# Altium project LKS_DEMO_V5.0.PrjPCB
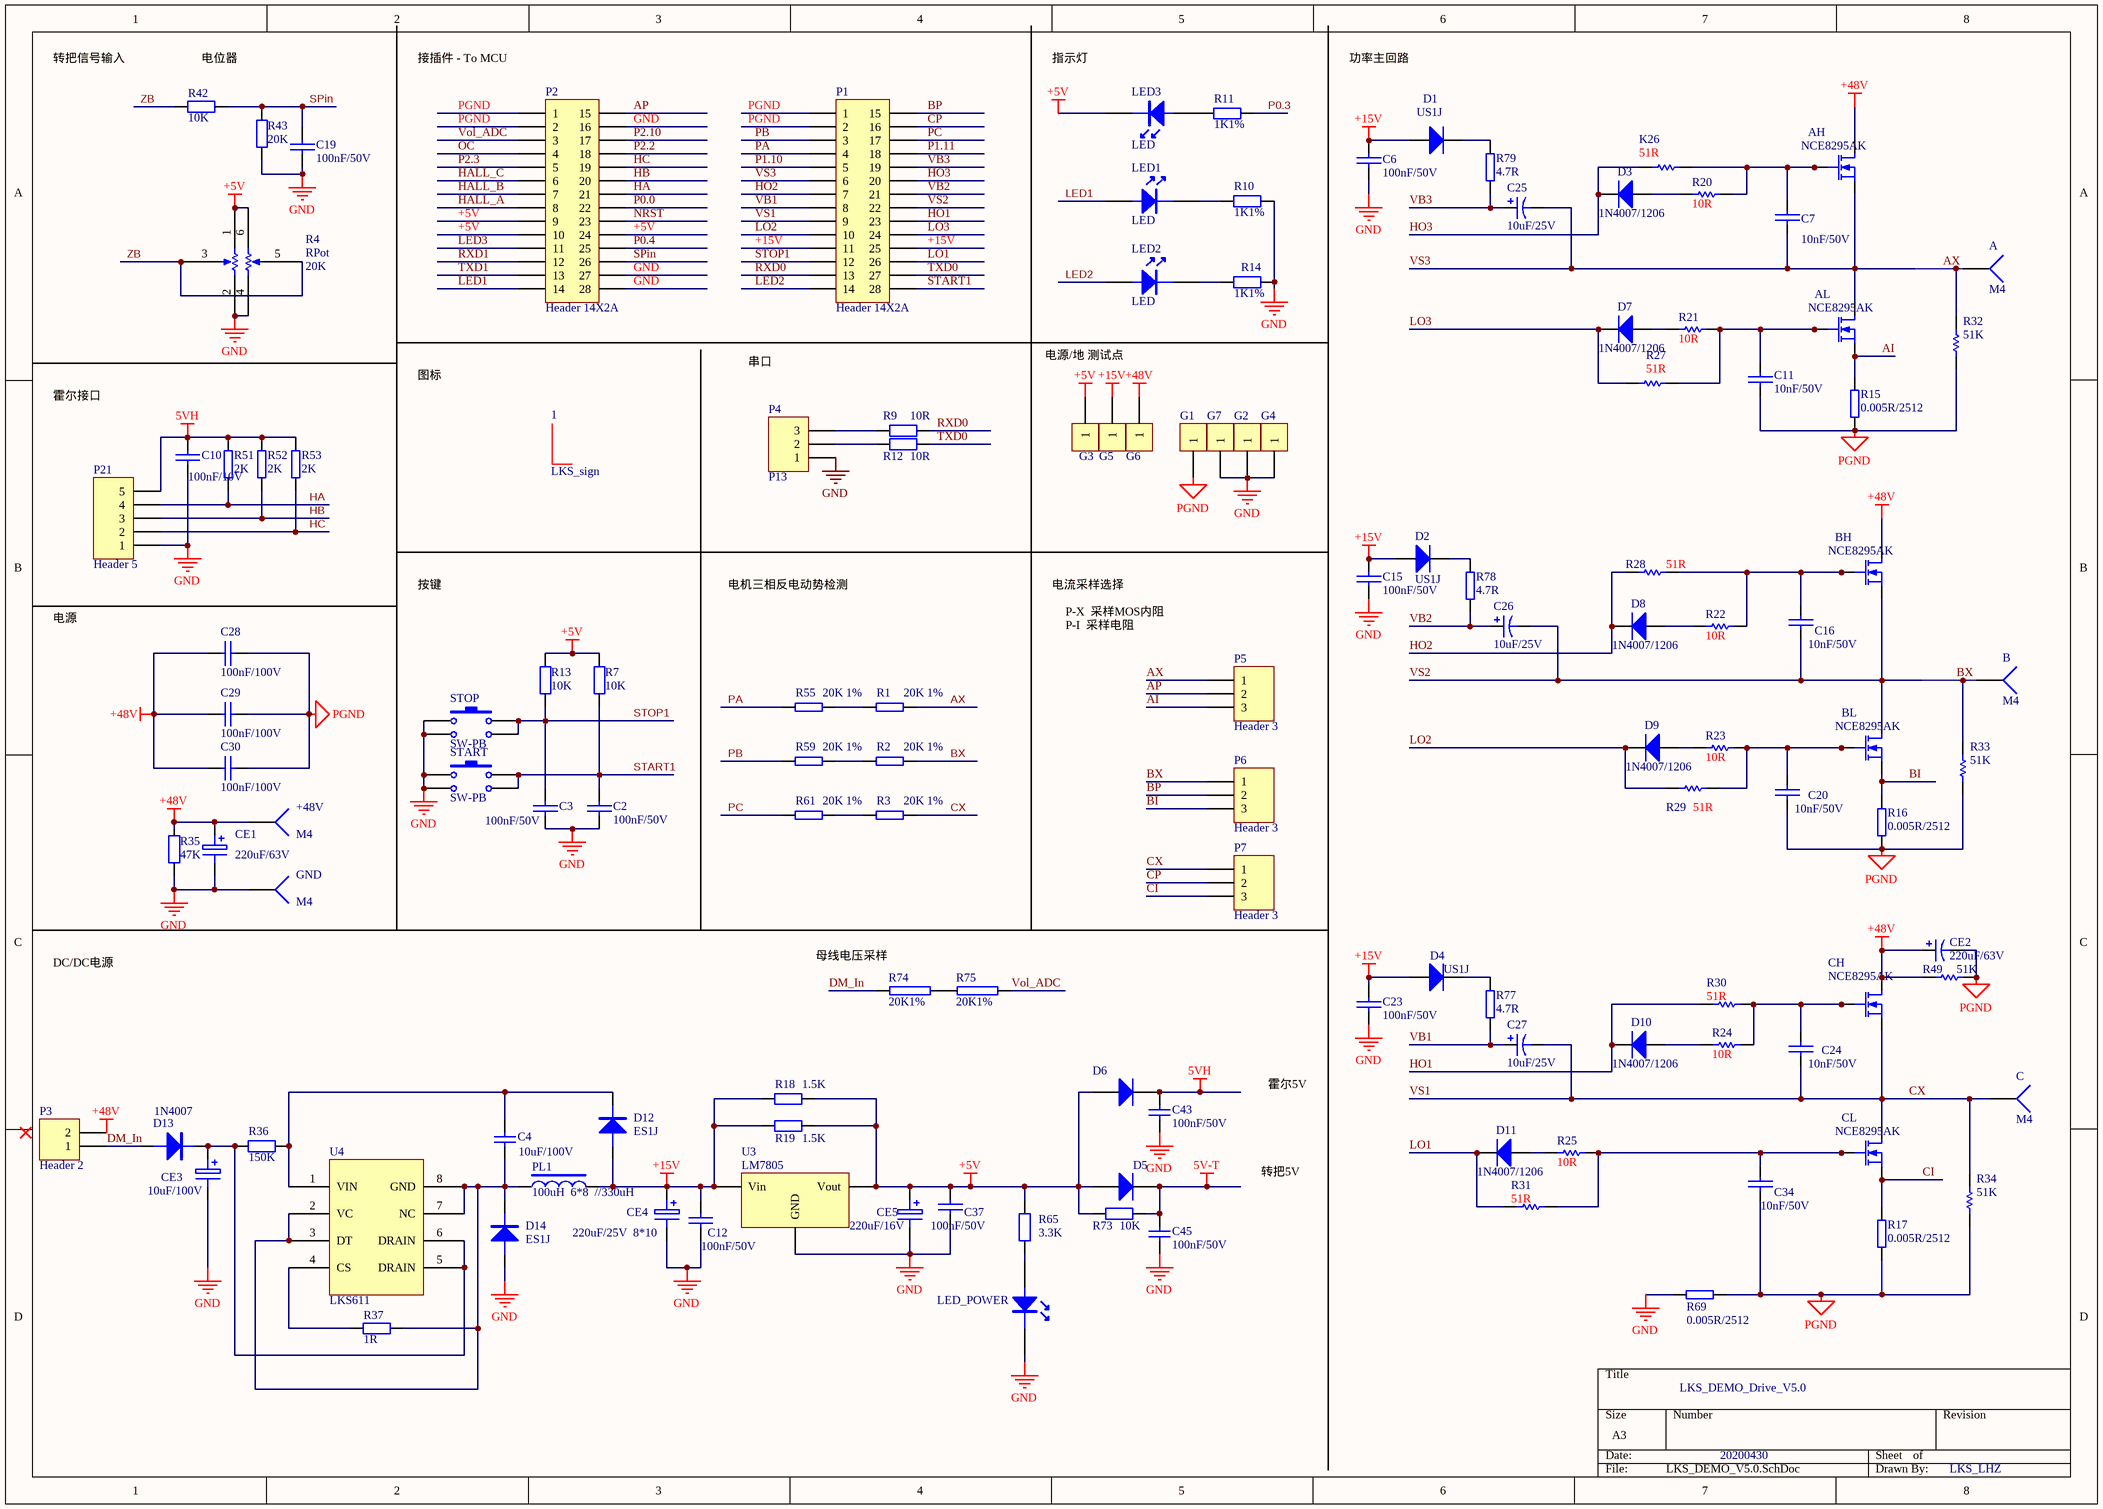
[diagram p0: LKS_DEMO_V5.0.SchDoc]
1 sheet, 130 parts. Net scope: global (net labels, ports and power ports of the same name join across sheets).
Board file: LKS_DEMO_V5.0.PcbDoc

## Sheet LKS_DEMO_V5.0.SchDoc
size A3

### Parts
1  LKS_sign  [LKS_LOGO2]
+48V  M4  [M4_Conector]
A  M4  [M4_Conector]
AH  NCE8295AK  [TO-252]
AL  NCE8295AK  [TO-252]
B  M4  [M4_Conector]
BH  NCE8295AK  [TO-252]
BL  NCE8295AK  [TO-252]
C  M4  [M4_Conector]
C2  100nF/50V  [0603C]
C3  100nF/50V  [0603C]
C4  10uF/100V  [1206]
C6  100nF/50V  [0603C]
C7  10nF/50V  [0603C]
C10  100nF/10V  [0603C]
C11  10nF/50V  [0603C]
C12  100nF/50V  [0603C]
C15  100nF/50V  [0603C]
C16  10nF/50V  [0603C]
C19  100nF/50V  [0603C]
C20  10nF/50V  [0603C]
C23  100nF/50V  [0603C]
C24  10nF/50V  [0603C]
C25  10uF/25V  [1206]
C26  10uF/25V  [1206]
C27  10uF/25V  [1206]
C28  100nF/100V  [0805C]
C29  100nF/100V  [0805C]
C30  100nF/100V  [0805C]
C34  10nF/50V  [0603C]
C37  100nF/50V  [0603C]
C43  100nF/50V  [0603C]
C45  100nF/50V  [0603C]
CE1  220uF/63V  [220uF/25V 12.5*12.5]
CE2  220uF/63V  [220uF/25V 12.5*12.5]
CE3  10uF/100V  [220UF/25V paster8*10]
CE4  220uF/25V  8*10  [220UF/25V paster8*10]
CE5  220uF/16V  [220UF/16V paster6.3*7.7 - duplicate]
CH  NCE8295AK  [TO-252]
CL  NCE8295AK  [TO-252]
D1  US1J  [SMA金丰]
D2  US1J  [SMA金丰]
D3  1N4007/1206  [D1206]
D4  US1J  [SMA金丰]
D5  1N4007  [D1206]  (value not drawn)
D6  1N4007  [D1206]  (value not drawn)
D7  1N4007/1206  [D1206]
D8  1N4007/1206  [D1206]
D9  1N4007/1206  [D1206]
D10  1N4007/1206  [D1206]
D11  1N4007/1206  [D1206]
D12  ES1J  [DO-214AC]
D13  1N4007  [DO-214AC]
D14  ES1J  [DO-214AC]
G1  PAD1.2  [PAD1.2]  (value not drawn)
G2  PAD1.2  [PAD1.2]  (value not drawn)
G3  PAD1.2  [PAD1.2]  (value not drawn)
G4  PAD1.2  [PAD1.2]  (value not drawn)
G5  PAD1.2  [PAD1.2]  (value not drawn)
G6  PAD1.2  [PAD1.2]  (value not drawn)
G7  PAD1.2  [PAD1.2]  (value not drawn)
GND  M4  [M4_Conector]
K26  51R  [0805R]
LED1  LED  [SOD323]
LED2  LED  [SOD323]
LED3  LED  [SOD323]
LED_POWER  LED_R  [SOD323]  (value not drawn)
P1  Header 14X2A  [HDR2X14_CEN]
P2  Header 14X2A  [HDR2X14_CEN]
P3  Header 2  [HDR1X2]
P4  P13  [2.54-XH-3A-180]
P5  Header 3  [HDR1X3]
P6  Header 3  [HDR1X3]
P7  Header 3  [HDR1X3]
P21  Header 5  [2.54-XH-5A-180]
PL1  100uH  6*8  //330uH  [L_DIP_6*8MM]
R1  20K 1%  [0805R]
R2  20K 1%  [0805R]
R3  20K 1%  [0805R]
R4  RPot  value 20K  [RK097-W]
R7  10K  [0603R]
R9  10R  [0603R]
R10  1K1%  [0603R]
R11  1K1%  [0603R]
R12  10R  [0603R]
R13  10K  [0603R]
R14  1K1%  [0603R]
R15  0.005R/2512  [2512]
R16  0.005R/2512  [2512]
R17  0.005R/2512  [2512]
R18  1.5K  [0805R]
R19  1.5K  [0805R]
R20  10R  [0805R]
R21  10R  [0805R]
R22  10R  [0805R]
R23  10R  [0805R]
R24  10R  [0805R]
R25  10R  [0805R]
R27  51R  [0805R]
R28  51R  [0805R]
R29  51R  [0805R]
R30  51R  [0805R]
R31  51R  [0805R]
R32  51K  [0805R]
R33  51K  [0805R]
R34  51K  [0805R]
R35  47K  [1206R]
R36  150K  [0805R]
R37  1R  [1206]
R42  10K  [0603R]
R43  20K  [0603R]
R49  51K  [0805R]
R51  2K  [0603R]
R52  2K  [0603R]
R53  2K  [0603R]
R55  20K 1%  [0805R]
R59  20K 1%  [0805R]
R61  20K 1%  [0805R]
R65  3.3K  [0603R]
R69  0.005R/2512  [2512]
R73  10K  [0603R]
R74  20K1%  [0603R]
R75  20K1%  [0603R]
R77  4.7R  [0805r]
R78  4.7R  [0805r]
R79  4.7R  [0805r]
START  SW-PB  [SW-PB  12*12]
STOP  SW-PB  [SW-PB  12*12]
U3  LM7805  [SOT-89]
U4  LKS611

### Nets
5V-T: C45.2 D5.2(K) R73.2
5VH: C10.1 C43.2 D6.2(K) P21.5 R51.2 R52.2 R53.2
+5V: C37.2 CE5.1 D5.1(A) D6.1(A) G3.1 LED3.2(K) P2.9 P2.10 P2.24 R4.1(TOP) R4.6(TOP) R7.1 R13.2 R18.2 R19.2 R65.1 R73.1 U3.1(Vout)
+15V: C6.2 C12.1 C15.2 C23.2 CE4.1 D1.1(A) D2.1(A) D4.1(A) D12.1 G5.1 P1.11 P1.25 PL1.1 R18.1 R19.1 U3.3(Vin)
+48V: +48V.1 AH.2(D) BH.2(D) C28.2 C29.2 C30.2 CE1.1 CE2.1 CH.2(D) G6.1 P3.2 R35.1 R49.1
GND: C2.1 C3.2 C6.1 C10.2 C12.2 C15.1 C19.1 C23.1 C37.1 C43.1 C45.1 CE1.2 CE3.2 CE4.2 CE5.2 D14.1 G2.1 G4.1 G7.1 GND.1 LED_POWER.2(K) P2.16 P2.27 P2.28 P4.1 P21.1 R4.2(TAP) R4.4(BOT) R10.2 R14.2 R35.2 R43.1 R69.2 START.1 START.3 STOP.1 STOP.3 U3.2(GND)
PGND: C11.2 C20.2 C28.1 C29.1 C30.1 C34.2 CE2.2 G1.1 P1.1 P1.2 P2.1 P2.2 R15.2 R16.1 R17.2 R32.1 R33.1 R34.1 R49.2 R69.1
AI: AL.3(S) P5.3 R15.1
AP: P2.15 P5.2
AX: A.1 AH.3(S) AL.2(D) C7.2 C25.2 P1.6 P5.1 R1.2 R32.2  [also labelled VS3]
BI: BL.3(S) P6.3 R16.2
BP: P1.15 P6.2
BX: B.1 BH.3(S) BL.2(D) C16.2 C26.2 P1.22 P6.1 R2.2 R33.2  [also labelled VS2]
CI: CL.3(S) P7.3 R17.1
CP: P1.16 P7.2
CX: C.1 C24.2 C27.2 CH.3(S) CL.2(D) P1.9 P7.1 R3.2 R34.2  [also labelled VS1]
DM_In: D13.1 P3.1 R74.1
HA: P2.21 P21.4 R51.1
HALL_A: P2.8
HALL_B: P2.7
HALL_C: P2.6
HB: P2.20 P21.3 R52.1
HC: P2.19 P21.2 R53.1
HO1: D10.2(K) P1.23 R30.1
HO2: D8.2(K) P1.7 R28.1
HO3: D3.2(K) K26.1 P1.20
LED1: LED1.1(A) P2.14
LED2: LED2.1(A) P1.14
LED3: P2.11
LO1: D11.2(K) P1.26 R31.1
LO2: D9.2(K) P1.10 R29.1
LO3: D7.2(K) P1.24 R27.1
NRST: P2.23
OC: P2.4
P0.0: P2.22
P0.3: R11.2
P0.4: P2.25
P1.10: P1.5
P1.11: P1.18
P2.2: P2.18
P2.3: P2.5
P2.10: P2.17
PA: P1.4 R55.1
PB: P1.3 R59.1
PC: P1.17 R61.1
RXD0: P1.13 R9.1
RXD1: P2.12
SPin: C19.2 P2.26 R42.2 R43.2
START1: C2.2 P1.28 R7.2 START.2 START.4
STOP1: C3.1 P1.12 R13.1 STOP.2 STOP.4
TXD0: P1.27 R12.2
TXD1: P2.13
VB1: C27.1 P1.8 R77.1
VB2: C26.1 P1.21 R78.1
VB3: C25.1 P1.19 R79.1
Vol_ADC: P2.3 R75.2
ZB: R4.3(BOT) R4.5(TAP) R42.1
NetAH_1: AH.1(G) C7.1 K26.2 R20.1
NetAL_1: AL.1(G) C11.1 R21.1 R27.2
NetBH_1: BH.1(G) C16.1 R22.1 R28.2
NetBL_1: BL.1(G) C20.1 R23.1 R29.2
NetC4_1: C4.1 D12.2 R36.1 U4.1(VIN)
NetC4_2: C4.2 D14.2 PL1.2 R37.2 U4.2(VC) U4.3(DT) U4.7(NC) U4.8(GND)
NetC24_1: C24.1 CH.1(G) R24.1 R30.2
NetC34_1: C34.1 CL.1(G) R25.1 R31.2
NetCE3_1: CE3.1 D13.2 R36.2 U4.5(DRAIN) U4.6(DRAIN)
NetD1_2: D1.2(K) R79.2
NetD2_2: D2.2(K) R78.2
NetD3_1: D3.1(A) R20.2
NetD4_2: D4.2(K) R77.2
NetD7_1: D7.1(A) R21.2
NetD8_1: D8.1(A) R22.2
NetD9_1: D9.1(A) R23.2
NetD10_1: D10.1(A) R24.2
NetD11_1: D11.1(A) R25.2
NetLED1_2: LED1.2(K) R10.1
NetLED2_2: LED2.2(K) R14.1
NetLED3_1: LED3.1(A) R11.1
NetLED_POWER_1: LED_POWER.1(A) R65.2
NetP4_2: P4.2 R12.1
NetP4_3: P4.3 R9.2
NetR1_1: R1.1 R55.2
NetR2_1: R2.1 R59.2
NetR3_1: R3.1 R61.2
NetR37_1: R37.1 U4.4(CS)
NetR74_2: R74.2 R75.1

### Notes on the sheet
- 转把信号输入
- (near R42) 电位器
- 接插件 - To MCU
- 指示灯
- 功率主回路
- 图标
- 串口
- 电源/地 测试点
- 霍尔接口
- 按键
- 电机三相反电动势检测
- 电流采样选择
- 电源
- P-X  采样MOS内阻
- P-I  采样电阻
- DC/DC电源
- (near R74) 母线电压采样
- LKS_DEMO_Drive_V5.0
- 20200430
- LKS_LHZ
- Labels drawn without touching a wire or pin: 转把5V, 霍尔5V

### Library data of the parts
+48V A B C GND = Socket
AH AL BH BL CH CL = MOS
C2 C3 C7 C10-C12 C16 C20 C24 C28-C30 C34 = CAP: Capacitor
C4 = Cap: Capacitor
C6 C15 C19 C23 C37 = C: Capacitor
C25-C27 = Cap Pol1: Polarized Capacitor (Radial); Value: 47uF/50V
C43 C45 = Cap: Capacitor; Value: 104
CE1 CE3-CE5 = CD: Electrolytic Capacitor
CE2 = Cap Pol1: Polarized Capacitor (Radial); Value: 1uF
D1-D4 D7-D11 = Diode: Default Diode
D5 D6 = Diode 1N4007: 1 Amp General Purpose Rectifier
D12-D14 = D: Diode
G1-G7 = CON1: Connector
K26 R20-R25 R27-R31 = Res1: Resistor; Value: 150
LED_POWER = LED
P1 P2 = Header 14X2A: Header, 14-Pin, Dual row
P3 = Header 2: Header, 2-Pin
P4-P7 = Header 3: Header, 3-Pin
P21 = Header 5: Header, 5-Pin
PL1 = L
R1-R3 R51-R53 R55 R59 R61 = RES/1
R4 = RPot: Potentiometer; Sim Note: Enter the Resistance value and the set point into parameter fields.; Set Position: 0.5
R7 R9 R13 R36 R37 R73 = Res2: Resistor
R10 R11 R14 = Res2: Resistor; Value: 10K
R12 = Res2: Resistor; Value: 100R
R15-R17 R69 R77-R79 = RES2短
R18 R19 R35 R42 R43 = Res: Resistor; Value: K
R32-R34 = Res1: Resistor; Value: 10K
R49 = Res1: Resistor; Value: 47K
R65 = Res2: Resistor; Value: 510R
R74 R75 = R
START STOP = SW-PB: Switch
U3 = VOL-78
